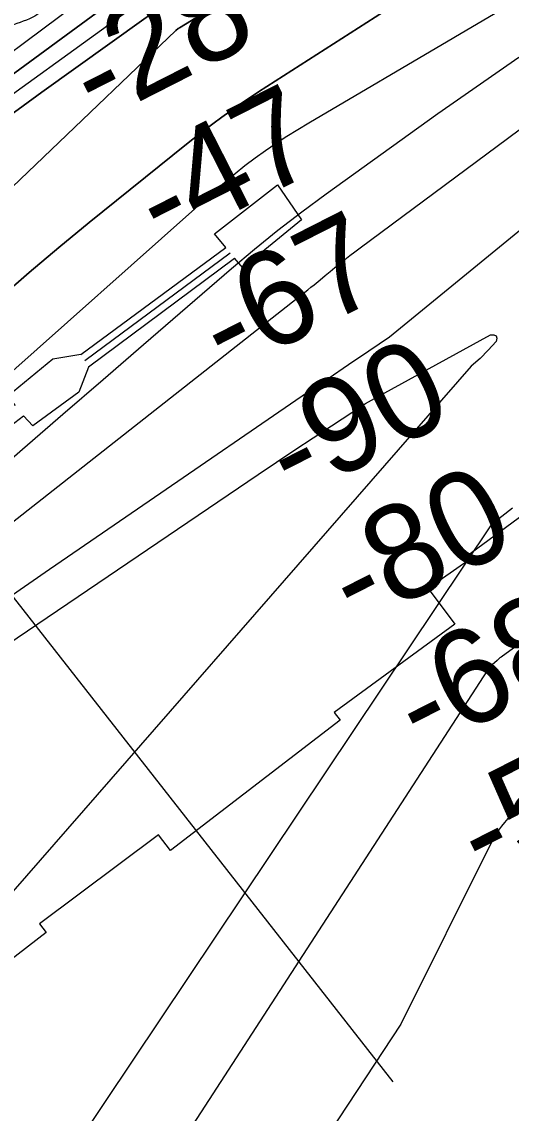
# Model space of a CAD drawing. Extents: x 3297753 to 3335611, y 652252 to 677623.
# Drawn here: x 3314835 to 3315180, y 658590 to 659359 of the extents above; entities that cross this region are included whole.
import ezdxf

# ---------------------------------------------------------------- set-up
doc = ezdxf.new("R2010")
doc.units = 0
for name, color, linetype in [('V-CHAN-DOCK', 7, 'Continuous'), ('V-RIVR-EDGE', 7, 'Continuous'), ('V-RIVR-RANG', 7, 'Continuous'), ('V-RRAP-RVMT', 7, 'Continuous'), ('V-TOPO-DPTH', 7, 'Continuous'), ('V-TOPO-MAJR', 7, 'Continuous'), ('V-TOPO-MINR', 7, 'Continuous'), ('V-UTIL-LINE', 7, 'Continuous')]:
    doc.layers.add(name, color=color, linetype=linetype)

msp = doc.modelspace()

# ---------------------------------------------------------------- linework, layer by layer
at = {"layer": 'V-CHAN-DOCK'}
for p, q in [((3314876.75, 659124.14), (3314978.7, 659199.76)), ((3314881.95, 659115.67), (3314984.91, 659192.25)), ((3314784.47, 659041.35), (3314836.26, 659081.09))]:
    msp.add_line(p, q, dxfattribs=at)
for points in [[(3314978.7, 659199.76), (3314970.82, 659209.4), (3315015.15, 659243.72), (3315032.01, 659219.11), (3314990.66, 659185.25), (3314984.91, 659192.25)], [(3314830.66, 659088.39), (3314825.06, 659094.8), (3314856.88, 659121.24), (3314876.65, 659124.46), (3314876.75, 659124.14)], [(3314881.95, 659115.67), (3314882.17, 659115.26), (3314875.2, 659097.8), (3314842.93, 659073.96), (3314836.26, 659081.09)]]:
    msp.add_lwpolyline(points, dxfattribs=at)
at = {"layer": 'V-RIVR-EDGE'}
msp.add_spline([(3319472.94, 662096.79), (3319451.36, 662084.83), (3319431.44, 662073.27), (3319412.76, 662065.44), (3319386.64, 662059.7), (3319355.13, 662056.05), (3319321.53, 662047.43), (3319286.69, 662035.91), (3319261.79, 662024.37), (3319253.91, 662022.31), (3319243.96, 662022.34), (3319236.91, 662020.28), (3319220.3, 662007.06), (3319214.06, 661999.2), (3319197.88, 661992.61), (3319174.65, 661985.21), (3319135.25, 661974.53), (3319095.84, 661962.6), (3319061.83, 661950.67), (3319035.69, 661940.78), (3319017.02, 661932.54), (3319004.15, 661925.11), (3318977.6, 661914.4), (3318949.4, 661908.67), (3318929.07, 661903.33), (3318893.41, 661894.3), (3318836.17, 661878.69), (3318802.16, 661869.66), (3318784.32, 661864.31), (3318761.1, 661859.4), (3318735.37, 661848.27), (3318707.16, 661836.32), (3318683.94, 661831.82), (3318667.77, 661829.78), (3318647.86, 661824.86), (3318612.18, 661812.51), (3318583.56, 661801.39), (3318550.78, 661789.45), (3318517.19, 661780.83), (3318486.91, 661770.55), (3318459.1, 661757.77), (3318437.11, 661748.7), (3318401.09, 661732.56), (3318376.27, 661719.66), (3318350.33, 661712.4), (3318322.69, 661702.89), (3318295.62, 661690.56), (3318275.88, 661686.66), (3318257.84, 661681.07), (3318243.73, 661673.22), (3318214.4, 661661.46), (3318180.55, 661645.76), (3318148.4, 661630.07), (3318131.47, 661619.4), (3318111.14, 661604.8), (3318079.51, 661575.01), (3318056.38, 661560.42), (3318032.66, 661542.45), (3318016.3, 661532.35), (3317961.53, 661489.66), (3317862.74, 661415.52), (3317830, 661391.93), (3317829.43, 661388.56), (3317827.16, 661382.93), (3317810.8, 661375.64), (3317785.97, 661359.92), (3317761.13, 661342.52), (3317743.62, 661322.84), (3317726.09, 661300.91), (3317708.57, 661278.97), (3317696.72, 661270.55), (3317673.58, 661255.39), (3317601.32, 661201.48), (3317560.67, 661171.71), (3317529.07, 661153.2), (3317513.82, 661140.27), (3317483.9, 661117.24), (3317464.15, 661105.46), (3317423.52, 661083.02), (3317409.43, 661079.11), (3317401.54, 661079.13), (3317375.02, 661065.67), (3317364.3, 661058.94), (3317348.5, 661051.09), (3317330.46, 661046.62), (3317307.32, 661033.16), (3317289.27, 661024.75), (3317263.88, 661012.42), (3317240.77, 661008.53), (3317230.05, 661004.05), (3317228.35, 661000.11), (3317221.59, 660998.43), (3317196.21, 660991.17), (3317170.27, 660981.66), (3317149.41, 660978.33), (3317103.16, 660960.97), (3317073.27, 660949.78), (3317034.34, 660929.59), (3316995.97, 660909.96), (3316948.02, 660886.98), (3316914.74, 660873.53), (3316885.97, 660860.65), (3316880.89, 660856.15), (3316871.29, 660848.28), (3316865.65, 660846.61), (3316855.51, 660846.63), (3316850.44, 660846.65), (3316844.22, 660840.46), (3316839.71, 660839.91), (3316835.77, 660840.48), (3316830.69, 660836.55), (3316818.84, 660828.69), (3316813.76, 660828.14), (3316808.13, 660827.03), (3316803.62, 660827.04), (3316796.84, 660818.6), (3316784.98, 660809.62), (3316774.82, 660802.88), (3316771.42, 660796.13), (3316765.18, 660779.24), (3316755.55, 660759.54), (3316745.94, 660744.35), (3316732.38, 660728.61), (3316712.63, 660717.95), (3316683.85, 660703.37), (3316676.52, 660701.13), (3316664.67, 660695.53), (3316651.68, 660680.34), (3316633.05, 660666.87), (3316616.12, 660656.2), (3316590.15, 660637.11), (3316544.42, 660603.41), (3316510, 660580.96), (3316472.73, 660551.75), (3316428.71, 660523.12), (3316390.32, 660495.6), (3316363.8, 660477.64), (3316349.69, 660469.78), (3316341.23, 660464.73), (3316335.03, 660464.75), (3316325.45, 660464.77), (3316313.61, 660461.42), (3316289.93, 660456.97), (3316257.21, 660443.53), (3316237.47, 660436.25), (3316207.01, 660423.93), (3316177.1, 660405.41), (3316154.53, 660393.07), (3316131.95, 660375.09), (3316110.5, 660362.19), (3316095.27, 660353.21), (3316080.02, 660338.03), (3316051.22, 660312.74), (3316013.92, 660270.58), (3315988.5, 660245.84), (3315960.26, 660217.18), (3315939.93, 660200.89), (3315925.81, 660185.14), (3315911.13, 660173.91), (3315895.32, 660159.86), (3315882.88, 660145.8), (3315867.63, 660130.06), (3315849.01, 660119.97), (3315837.71, 660109.29), (3315808.9, 660080.06), (3315786.88, 660062.08), (3315758.09, 660038.49), (3315733.81, 660018.83), (3315725.32, 660002.51), (3315692.01, 659976.67), (3315659.82, 659949.14), (3315603.36, 659904.2), (3315571.16, 659873.28), (3315569.47, 659873.29), (3315558.76, 659868.81), (3315547.47, 659863.2), (3315527.7, 659844.09), (3315506.25, 659828.37), (3315477.47, 659812.1), (3315461.12, 659805.94), (3315440.8, 659793.59), (3315429.5, 659781.79), (3315402.4, 659758.19), (3315361.76, 659731.8), (3315304.2, 659696.45), (3315255.66, 659666.7), (3315169.91, 659624.65), (3315140.01, 659611.76), (3315123.65, 659603.35), (3315098.82, 659588.76), (3315044.63, 659551.14), (3314989.87, 659507.33), (3314954.29, 659474.73), (3314933.97, 659462.39), (3314926.06, 659452.83), (3314915.88, 659440.45), (3314897.81, 659423.59), (3314866.75, 659396.06), (3314844.73, 659376.39), (3314848.66, 659370.75), (3314824.95, 659355.03), (3314801.82, 659342.69), (3314762.32, 659320.81), (3314730.16, 659303.42), (3314710.97, 659290.51), (3314664.68, 659256.25), (3314628.56, 659235.49), (3314603.16, 659218.09), (3314584.55, 659209.68), (3314564.82, 659208.04), (3314555.8, 659204.68), (3314546.76, 659196.25), (3314528.11, 659174.88), (3314492.47, 659118.62), (3314473.82, 659095), (3314450.67, 659074.77), (3314428.65, 659060.18), (3314423, 659054.56), (3314416.22, 659044.43), (3314398.14, 659027.57), (3314375.56, 659007.9), (3314366.53, 659005.11), (3314353.57, 659002.32), (3314347.36, 658997.27), (3314346.77, 658988.82), (3314351.26, 658983.17), (3314350.68, 658974.16), (3314342.76, 658961.78), (3314329.22, 658955.05), (3314311.71, 658940.44), (3314310, 658930.31), (3314294.2, 658921.89), (3314283.48, 658914.59), (3314276.12, 658903.91), (3314272.72, 658896.02), (3314237.73, 658871.32), (3314206.69, 658853.36), (3314198.23, 658851.13), (3314192.03, 658850.58), (3314180.19, 658846.1), (3314172.28, 658836.54), (3314164.36, 658823.6), (3314142.35, 658810.13), (3314120.89, 658792.72), (3314097.19, 658778.69), (3314086.46, 658769.14), (3314082.5, 658762.95), (3314080.22, 658754.5), (3314072.33, 658750.01), (3314036.79, 658734.32), (3314006.33, 658722), (3313997.3, 658716.39), (3313939.72, 658673.71), (3313888.34, 658634.95), (3313863.5, 658615.29), (3313820.61, 658586.66), (3313772.64, 658558.04), (3313732, 658532.78), (3313718.46, 658524.37), (3313711.13, 658521.57), (3313702.68, 658521.59), (3313693.09, 658518.79), (3313674.48, 658511.51), (3313646.82, 658494.68), (3313626.5, 658478.95), (3313619.73, 658475.02), (3313610.12, 658464.34), (3313605.01, 658449.14), (3313597.11, 658444.65), (3313577.92, 658428.92), (3313554.76, 658407.56), (3313537.8, 658387.32), (3313525.35, 658364.25), (3313506.11, 658331.61), (3313489.72, 658309.68)], degree=3, dxfattribs=at)
at = {"layer": 'V-RIVR-RANG'}
msp.add_line((3314245.79, 659698.23), (3315096.4, 658611.56), dxfattribs=at)
at = {"layer": 'V-RRAP-RVMT'}
for p, q in [((3315206.87, 659025.22), (3315147.44, 658981.22)), ((3315149.17, 658978.73), (3315121.23, 658959.37)), ((3315147.44, 658981.22), (3315149.17, 658978.73)), ((3315121.23, 658959.37), (3315139.98, 658934.3)), ((3315139.98, 658934.3), (3315055.04, 658872.01)), ((3315055.04, 658872.01), (3315059.28, 658866.55)), ((3315059.28, 658866.55), (3314939.91, 658774.7)), ((3314931.31, 658785.63), (3314847.47, 658723.09)), ((3314939.91, 658774.7), (3314931.31, 658785.63)), ((3314847.47, 658723.09), (3314852.34, 658716.98)), ((3314852.34, 658716.98), (3314768.87, 658652.39))]:
    msp.add_line(p, q, dxfattribs=at)
at = {"layer": 'V-TOPO-DPTH'}
for points in [[(3314301.01, 658763.88), (3314338.56, 658796.49), (3314376.07, 658829.14), (3314413.55, 658861.81), (3314450.94, 658894.6), (3314488.23, 658927.5), (3314525.37, 658960.57), (3314562.4, 658993.75), (3314578.83, 659008.54), (3314623.82, 659049.41), (3314668.55, 659090.55), (3314712.9, 659132.1), (3314757, 659173.93), (3314943.66, 659352.57), (3314945.2, 659353.88), (3314946.06, 659354.47), (3314946.12, 659354.51), (3315567.61, 659735.18)], [(3315567.61, 659735.18), (3314946.12, 659354.51), (3314946.06, 659354.47), (3314945.2, 659353.88), (3314943.66, 659352.57), (3314757, 659173.93), (3314712.9, 659132.1), (3314668.55, 659090.55), (3314623.82, 659049.41), (3314578.83, 659008.54), (3314562.4, 658993.75), (3314525.37, 658960.57), (3314488.23, 658927.5), (3314450.94, 658894.6), (3314413.55, 658861.81), (3314376.07, 658829.14), (3314338.56, 658796.49), (3314301.01, 658763.88)], [(3314231.52, 658758.66), (3314398.02, 658905.48), (3314452.29, 658953.84), (3314506.22, 659002.57), (3314559.64, 659051.86), (3314612.71, 659101.53), (3314677.26, 659162.56), (3314697.9, 659181.88), (3314718.66, 659201.07), (3314739.61, 659220.06), (3314760.69, 659238.91), (3314782.14, 659257.3), (3314803.96, 659275.23), (3314826.33, 659292.46), (3314849.08, 659309.23), (3314920.96, 659360.47), (3314929.07, 659366.16), (3314937.23, 659371.78), (3314945.48, 659377.28), (3314953.77, 659382.71), (3315252.63, 659575.1)], [(3315252.63, 659575.1), (3314953.77, 659382.71), (3314945.48, 659377.28), (3314937.23, 659371.78), (3314929.07, 659366.16), (3314920.96, 659360.47), (3314849.08, 659309.23), (3314826.33, 659292.46), (3314803.96, 659275.23), (3314782.14, 659257.3), (3314760.69, 659238.91), (3314739.61, 659220.06), (3314718.66, 659201.07), (3314697.9, 659181.88), (3314677.26, 659162.56), (3314612.71, 659101.53), (3314559.64, 659051.86), (3314506.22, 659002.57), (3314452.29, 658953.84), (3314398.02, 658905.48), (3314231.52, 658758.66)], [(3315188.38, 659571.58), (3315123.05, 659526.74), (3315057.54, 659482.16), (3314962.55, 659417.91), (3314944.48, 659405.54), (3314926.5, 659393.03), (3314908.67, 659380.32), (3314890.93, 659367.48), (3314751.49, 659265.31), (3314706.87, 659231.64), (3314662.91, 659197.17), (3314619.92, 659161.47), (3314577.6, 659124.97), (3314566.45, 659115.08), (3314530.34, 659082.75), (3314494.43, 659050.2), (3314458.81, 659017.32), (3314423.39, 658984.22), (3314387.93, 658951.18), (3314352.21, 658918.42), (3314316.09, 658886.1)], [(3314316.09, 658886.1), (3314352.21, 658918.42), (3314387.93, 658951.18), (3314423.39, 658984.22), (3314458.81, 659017.32), (3314494.43, 659050.2), (3314530.34, 659082.75), (3314566.45, 659115.08), (3314577.6, 659124.97), (3314619.92, 659161.47), (3314662.91, 659197.17), (3314706.87, 659231.64), (3314751.49, 659265.31), (3314890.93, 659367.48), (3314908.67, 659380.32), (3314926.5, 659393.03), (3314944.48, 659405.54), (3314962.55, 659417.91), (3315057.54, 659482.16), (3315123.05, 659526.74), (3315188.38, 659571.58)], [(3314161.79, 658590.48), (3314382.08, 658780.05), (3314445.14, 658834.51), (3314508.08, 658889.1), (3314570.85, 658943.9), (3314633.49, 658998.84), (3314717.41, 659072.7), (3314737.95, 659090.87), (3314758.44, 659109.1), (3314778.83, 659127.43), (3314799.17, 659145.83), (3314819.62, 659164.09), (3314840.28, 659182.11), (3314861.25, 659199.77), (3314882.43, 659217.18), (3314950.99, 659272.54), (3314963.36, 659282.21), (3314975.93, 659291.6), (3314988.8, 659300.57), (3315001.87, 659309.27), (3315201.42, 659437.47)], [(3315201.42, 659437.47), (3315001.87, 659309.27), (3314988.8, 659300.57), (3314975.93, 659291.6), (3314963.36, 659282.21), (3314950.99, 659272.54), (3314882.43, 659217.18), (3314861.25, 659199.77), (3314840.28, 659182.11), (3314819.62, 659164.09), (3314799.17, 659145.83), (3314778.83, 659127.43), (3314758.44, 659109.1), (3314737.95, 659090.87), (3314717.41, 659072.7), (3314633.49, 658998.84), (3314570.85, 658943.9), (3314508.08, 658889.1), (3314445.14, 658834.51), (3314382.08, 658780.05), (3314161.79, 658590.48)]]:
    msp.add_lwpolyline(points, dxfattribs=at)
at = {"layer": 'V-TOPO-MAJR'}
msp.add_lwpolyline([(3314297.89, 658660.72), (3314328.33, 658684.91), (3314358.79, 658709.09), (3314372.45, 658719.92), (3314409.55, 658749.75), (3314446.38, 658779.89), (3314482.82, 658810.5), (3314519, 658841.44), (3314565.37, 658881.6), (3314624.44, 658932.96), (3314683.38, 658984.47), (3314742.13, 659036.19), (3314800.76, 659088.06), (3314978.43, 659245.84), (3314985.29, 659251.71), (3314992.29, 659257.41), (3314999.49, 659262.86), (3315006.82, 659268.12), (3315014.31, 659273.18), (3315021.87, 659278.13), (3315029.54, 659282.91), (3315037.27, 659287.58), (3315649.97, 659648.56)], dxfattribs=at)
at = {"layer": 'V-TOPO-MINR'}
for points in [[(3315567.61, 659735.18), (3314946.12, 659354.51), (3314946.06, 659354.47), (3314945.2, 659353.88), (3314943.66, 659352.57), (3314757, 659173.93), (3314712.9, 659132.1), (3314668.55, 659090.55), (3314623.82, 659049.41), (3314578.83, 659008.54), (3314562.4, 658993.75), (3314525.37, 658960.57), (3314488.23, 658927.5), (3314450.94, 658894.6), (3314413.55, 658861.81), (3314376.07, 658829.14), (3314338.56, 658796.49), (3314301.01, 658763.88)], [(3315203.83, 659602.62), (3315156.79, 659569.42), (3315109.65, 659536.36), (3315062.37, 659503.5), (3315014.99, 659470.79), (3314967.46, 659438.13), (3314943.86, 659421.72), (3314920.39, 659405.14), (3314897.11, 659388.3), (3314873.94, 659371.29), (3314702.14, 659243.63), (3314646.84, 659201.41), (3314592.3, 659158.25), (3314538.91, 659113.67), (3314486.28, 659068.16), (3314436.25, 659023.73), (3314409.33, 658999.6), (3314382.55, 658975.31), (3314356, 658950.77), (3314329.6, 658926.07), (3314303.15, 658901.42)], [(3315252.63, 659575.1), (3314953.77, 659382.71), (3314945.48, 659377.28), (3314937.23, 659371.78), (3314929.07, 659366.16), (3314920.96, 659360.47), (3314849.08, 659309.23), (3314826.33, 659292.46), (3314803.96, 659275.23), (3314782.14, 659257.3), (3314760.69, 659238.91), (3314739.61, 659220.06), (3314718.66, 659201.07), (3314697.9, 659181.88), (3314677.26, 659162.56), (3314612.71, 659101.53), (3314559.64, 659051.86), (3314506.22, 659002.57), (3314452.29, 658953.84), (3314398.02, 658905.48), (3314231.52, 658758.66)], [(3315188.38, 659571.58), (3315123.05, 659526.74), (3315057.54, 659482.16), (3314962.55, 659417.91), (3314944.48, 659405.54), (3314926.5, 659393.03), (3314908.67, 659380.32), (3314890.93, 659367.48), (3314751.49, 659265.31), (3314706.87, 659231.64), (3314662.91, 659197.17), (3314619.92, 659161.47), (3314577.6, 659124.97), (3314566.45, 659115.08), (3314530.34, 659082.75), (3314494.43, 659050.2), (3314458.81, 659017.32), (3314423.39, 658984.22), (3314387.93, 658951.18), (3314352.21, 658918.42), (3314316.09, 658886.1)], [(3315195.84, 659556.55), (3315114.49, 659502.64), (3314958.03, 659399.4), (3314945.04, 659390.71), (3314932.12, 659381.91), (3314919.32, 659372.94), (3314906.59, 659363.87), (3314800.46, 659287.17), (3314766.69, 659261.99), (3314733.45, 659236.16), (3314700.99, 659209.35), (3314669.06, 659181.88), (3314637.65, 659153.79), (3314606.41, 659125.5), (3314575.43, 659096.93), (3314544.63, 659068.18), (3314517.34, 659042.48), (3314472.8, 659000.98), (3314427.95, 658959.82), (3314382.64, 658919.16), (3314337.03, 658878.83), (3314119.14, 658688.34)], [(3314220.45, 658525.23), (3314645.55, 658826.7), (3314715.05, 658875.73), (3314784.72, 658924.52), (3314854.63, 658972.97), (3314924.71, 659021.18), (3315036.41, 659097.62), (3315050.77, 659107.42), (3315065.14, 659117.19), (3315079.54, 659126.92), (3315093.96, 659136.63), (3315485.38, 659457.4)], [(3315201.42, 659437.47), (3315001.87, 659309.27), (3314988.8, 659300.57), (3314975.93, 659291.6), (3314963.36, 659282.21), (3314950.99, 659272.54), (3314882.43, 659217.18), (3314861.25, 659199.77), (3314840.28, 659182.11), (3314819.62, 659164.09), (3314799.17, 659145.83), (3314778.83, 659127.43), (3314758.44, 659109.1), (3314737.95, 659090.87), (3314717.41, 659072.7), (3314633.49, 658998.84), (3314570.85, 658943.9), (3314508.08, 658889.1), (3314445.14, 658834.51), (3314382.08, 658780.05), (3314161.79, 658590.48)], [(3314224.02, 658546.97), (3314395.99, 658674.79), (3314493.99, 658748.25), (3314591.6, 658822.23), (3314688.61, 658896.99), (3314785.21, 658972.27), (3315032.38, 659166.49), (3315034.52, 659168.18), (3315036.66, 659169.89), (3315038.78, 659171.62), (3315040.9, 659173.35), (3315045.25, 659176.95), (3315048.72, 659179.81), (3315052.19, 659182.67), (3315055.67, 659185.52), (3315059.16, 659188.36), (3315062.67, 659191.17), (3315066.2, 659193.95), (3315069.77, 659196.69), (3315073.36, 659199.39), (3315281.86, 659354.11)], [(3314316.78, 658642.34), (3314380.49, 658691.53), (3314444.05, 658740.94), (3314507.36, 658790.65), (3314570.51, 658840.58), (3314691.7, 658936.87), (3314720.95, 658960.42), (3314749.99, 658984.23), (3314778.72, 659008.43), (3314807.23, 659032.87), (3314835.59, 659057.49), (3314863.97, 659082.1), (3314892.36, 659106.69), (3314920.77, 659131.26), (3314982.71, 659184.8), (3314998.97, 659198.48), (3315015.46, 659211.86), (3315032.3, 659224.8), (3315049.37, 659237.44), (3315128.04, 659294.06), (3315185.21, 659333.87)], [(3315169.25, 659137.38), (3315169.63, 659135.7), (3315169.23, 659133.39), (3315163.67, 659127.24), (3315157.84, 659121.4), (3315151.59, 659116), (3314422.03, 658279.84), (3314420.3, 658277.69), (3314418.64, 658275.48), (3314417.39, 658273.15), (3314416.55, 658270.74), (3314416.35, 658268.19), (3314416.57, 658265.56), (3314081.54, 657867.28), (3314006.71, 657811.76), (3313860.7, 657706.98), (3313831.22, 657686.25), (3313801.49, 657665.91), (3313771.36, 657646.14), (3313765.99, 657642.71)], [(3314217.3, 658508.16), (3315001.49, 659039.67), (3315014.37, 659048.35), (3315027.29, 659056.98), (3315040.25, 659065.54), (3315053.25, 659074.04), (3315075.17, 659088.31), (3315077.24, 659089.63), (3315081.45, 659092.14), (3315083.59, 659093.35), (3315165.33, 659138.13), (3315167.68, 659138.08), (3315169.25, 659137.38)], [(3315415.12, 659087.57), (3315172.64, 658910.93), (3315171.91, 658910.39), (3315170.51, 658909.25), (3315169.82, 658908.66), (3315166.29, 658905.48), (3315165.41, 658904.63), (3315163.85, 658902.75), (3315163.08, 658901.8), (3314609.65, 658048.15)], [(3315180.76, 659015.97), (3315165.59, 659004.22), (3314582.14, 658132.55)], [(3315182.19, 658802.14), (3315179.74, 658799.69), (3315177.37, 658797.16), (3315175.13, 658794.52), (3315172.98, 658791.8), (3315170.97, 658788.98), (3315169.07, 658786.09), (3315167.34, 658783.1), (3315165.7, 658780.04), (3315102.05, 658652.33), (3314634.33, 657941.92)]]:
    msp.add_lwpolyline(points, dxfattribs=at)
at = {"layer": 'V-UTIL-LINE'}
msp.add_line((3314879.37, 659119.93), (3314981.83, 659196), dxfattribs=at)

# ---------------------------------------------------------------- texts
at = {"layer": 'V-RIVR-RANG'}
for s, p in [('-28', (3314888.18, 659287.19)), ('-47', (3314934.3, 659198.46)), ('-67', (3314979.49, 659109.26)), ('-90', (3315026.32, 659020.89)), ('-80', (3315070.57, 658931.2)), ('-68', (3315116.93, 658842.59)), ('-56', (3315160.7, 658752.66))]:
    msp.add_text(s, height=67, rotation=27.00517, dxfattribs=at).set_placement(p)

doc.saveas('drawing.dxf')
